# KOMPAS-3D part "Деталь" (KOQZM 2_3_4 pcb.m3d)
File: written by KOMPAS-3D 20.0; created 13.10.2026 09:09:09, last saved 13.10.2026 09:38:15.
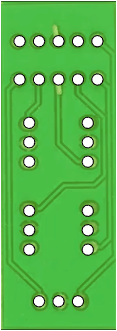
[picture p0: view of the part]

Document properties: Полное имя файла: D:\RicWork\Project-EPS32\box_compas\KOQZM 2_3_4 pcb.m3d

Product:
- Part/product: Деталь
    Масса: 0.00708008

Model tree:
1. Эскиз:1
2. Элемент выдавливания:1
     Расстояние 1 = 1.5
3. Эскиз:2  (with: Элемент выдавливания:1)
4. Элемент выдавливания:2
     Расстояние 2 = 1.5
5. Массив по сетке:1  (with: Элемент выдавливания:2, Эскиз:2)  (3 pattern instances)
     Шаг 1 = 2.54; Угол раствора = 90
6. Эскиз:3  (with: Элемент выдавливания:1)
7. Элемент выдавливания:3
     Расстояние 2 = 1.5
8. Массив по сетке:2  (with: Элемент выдавливания:3, Эскиз:3)  (3 pattern instances)
     Шаг 1 = 10; Угол раствора = 90; Шаг 2 = 2.54
9. Смещенная плоскость:1  (with: Элемент выдавливания:1)
     Расстояние = -7.5
10. Зеркальный массив:2
11. Экземпляр ( 1 )
12. Экземпляр ( 2 )  (with: Массив по сетке:2, Экземпляр ( 1 ), Элемент выдавливания:3)
13. Экземпляр ( 3 )  (with: Элемент выдавливания:3)
14. Эскиз:4  (with: Элемент выдавливания:1)
15. Элемент выдавливания:4
     Расстояние 2 = 1.5
16. Массив по сетке:3  (with: Элемент выдавливания:4, Эскиз:4)  (10 pattern instances)
     Шаг 1 = 2.54; Угол раствора = 90; Шаг 2 = 5

Referenced files in D:\RicWork\Project-EPS32\box_compas\: KOQZM 2_3_4 pcb.png
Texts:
  KOQZM 2_3_4 pcb.png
